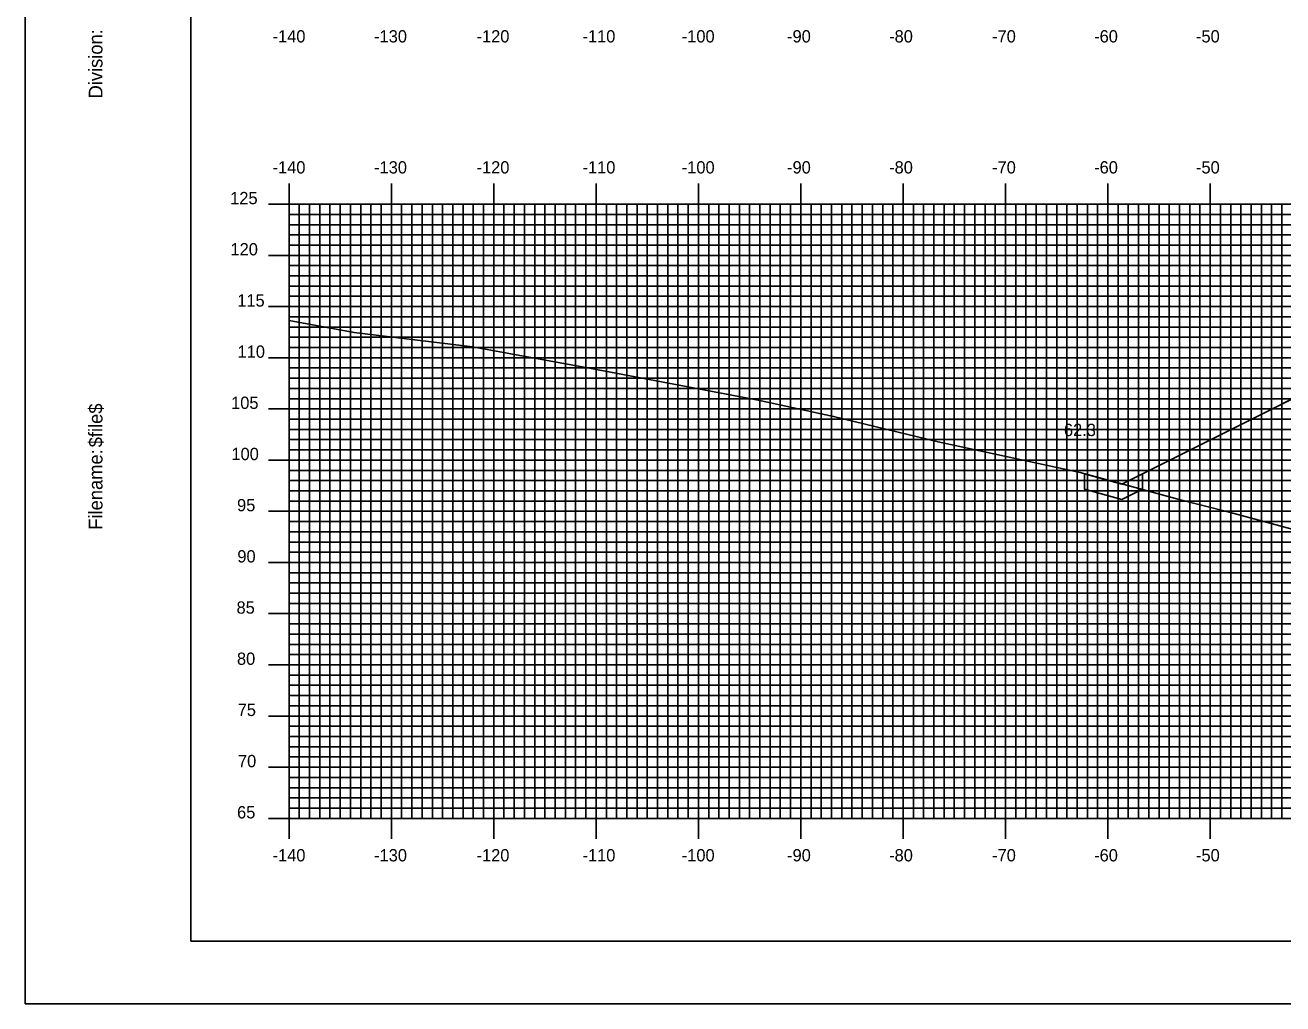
# Model space of a CAD drawing. Extents: x 858291 to 858634, y 364765 to 364985.
# Drawn here: x 858290.5 to 858413.4, y 364765.2 to 364860.8 of the extents above; entities that cross this region are included whole.
import ezdxf

# ---------------------------------------------------------------- set-up
doc = ezdxf.new("R2010")
doc.units = 0
for name, color, linetype in [('BORDER', 7, 'Continuous'), ('D_Roadway_Centerline', 7, 'Continuous'), ('D_Roadway_FinishedGrade', 7, 'Continuous'), ('D_Roadway_SlopeLines', 7, 'Continuous'), ('D_Text_Standard', 7, 'Continuous'), ('H_V ANNOTATION', 7, 'Continuous'), ('MAJOR', 7, 'Continuous'), ('MINOR', 7, 'Continuous'), ('PLOT BOUNDARY', 7, 'Continuous'), ('S_Roadway_Centerline', 7, 'Continuous')]:
    doc.layers.add(name, color=color, linetype=linetype)

msp = doc.modelspace()

# ---------------------------------------------------------------- linework, layer by layer
at = {"layer": 'BORDER'}
msp.add_lwpolyline([(858306.73, 364771.3), (858626.73, 364771.3), (858626.73, 364981.3), (858306.73, 364981.3)], close=True, dxfattribs=at)
at = {"layer": 'D_Roadway_Centerline'}
msp.add_lwpolyline([(858397.71, 364815.96), (858429.13, 364831.67), (858434.33, 364834.28), (858437.33, 364834.34), (858442.33, 364834.44), (858456.33, 364833.6), (858464.33, 364833.12), (858467.33, 364832.94), (858473.02, 364830.1), (858546.52, 364793.34)], dxfattribs=at)
at = {"layer": 'D_Roadway_FinishedGrade'}
for points in [[(858399.71, 364816.96), (858399.71, 364815.46), (858397.71, 364814.46), (858394.05, 364815.46), (858394.05, 364816.96), (858397.71, 364815.96)], [(858394.05, 364816.96), (858394.05, 364815.46), (858397.71, 364814.46), (858399.71, 364815.46), (858399.71, 364816.96), (858397.71, 364815.96)]]:
    msp.add_lwpolyline(points, close=True, dxfattribs=at)
at = {"layer": 'D_Roadway_SlopeLines'}
msp.add_lwpolyline([(858434.33, 364834.28), (858397.71, 364815.96)], dxfattribs=at)
at = {"layer": 'MAJOR'}
for p, q in [((858316.33, 364845.31), (858316.33, 364843.3)), ((858326.33, 364845.31), (858326.33, 364843.3)), ((858336.33, 364845.31), (858336.33, 364843.3)), ((858346.33, 364845.31), (858346.33, 364843.3)), ((858356.33, 364845.31), (858356.33, 364843.3)), ((858366.33, 364845.31), (858366.33, 364843.3)), ((858376.33, 364845.31), (858376.33, 364843.3)), ((858386.33, 364845.31), (858386.33, 364843.3)), ((858396.33, 364845.31), (858396.33, 364843.3)), ((858406.33, 364845.31), (858406.33, 364843.3)), ((858314.33, 364843.3), (858316.33, 364843.3)), ((858316.33, 364843.3), (858596.33, 364843.3)), ((858316.33, 364783.3), (858316.33, 364843.3)), ((858316.33, 364783.3), (858316.33, 364843.3)), ((858316.33, 364843.3), (858596.33, 364843.3)), ((858326.33, 364783.3), (858326.33, 364843.3)), ((858336.33, 364783.3), (858336.33, 364843.3)), ((858346.33, 364783.3), (858346.33, 364843.3)), ((858356.33, 364783.3), (858356.33, 364843.3)), ((858366.33, 364783.3), (858366.33, 364843.3)), ((858376.33, 364783.3), (858376.33, 364843.3)), ((858386.33, 364783.3), (858386.33, 364843.3)), ((858396.33, 364783.3), (858396.33, 364843.3)), ((858406.33, 364783.3), (858406.33, 364843.3)), ((858314.33, 364838.3), (858316.33, 364838.3)), ((858316.33, 364838.3), (858596.33, 364838.3)), ((858314.33, 364833.3), (858316.33, 364833.3)), ((858316.33, 364833.3), (858596.33, 364833.3)), ((858314.33, 364828.3), (858316.33, 364828.3)), ((858316.33, 364828.3), (858596.33, 364828.3)), ((858314.33, 364823.3), (858316.33, 364823.3)), ((858316.33, 364823.3), (858596.33, 364823.3)), ((858314.33, 364818.3), (858316.33, 364818.3)), ((858316.33, 364818.3), (858596.33, 364818.3)), ((858314.33, 364813.3), (858316.33, 364813.3)), ((858316.33, 364813.3), (858596.33, 364813.3)), ((858314.33, 364808.3), (858316.33, 364808.3)), ((858316.33, 364808.3), (858596.33, 364808.3)), ((858314.33, 364803.3), (858316.33, 364803.3)), ((858316.33, 364803.3), (858596.33, 364803.3)), ((858314.33, 364798.3), (858316.33, 364798.3)), ((858316.33, 364798.3), (858596.33, 364798.3)), ((858314.33, 364793.3), (858316.33, 364793.3)), ((858316.33, 364793.3), (858596.33, 364793.3)), ((858314.33, 364788.3), (858316.33, 364788.3)), ((858316.33, 364788.3), (858596.33, 364788.3)), ((858314.33, 364783.3), (858316.33, 364783.3)), ((858316.33, 364783.3), (858596.33, 364783.3)), ((858316.33, 364783.3), (858596.33, 364783.3)), ((858316.33, 364781.3), (858316.33, 364783.3)), ((858326.33, 364781.3), (858326.33, 364783.3)), ((858336.33, 364781.3), (858336.33, 364783.3)), ((858346.33, 364781.3), (858346.33, 364783.3)), ((858356.33, 364781.3), (858356.33, 364783.3)), ((858366.33, 364781.3), (858366.33, 364783.3)), ((858376.33, 364781.3), (858376.33, 364783.3)), ((858386.33, 364781.3), (858386.33, 364783.3)), ((858396.33, 364781.3), (858396.33, 364783.3)), ((858406.33, 364781.3), (858406.33, 364783.3))]:
    msp.add_line(p, q, dxfattribs=at)
at = {"layer": 'MINOR'}
for p, q in [((858316.33, 364842.3), (858596.33, 364842.3)), ((858316.33, 364842.3), (858318.34, 364842.3)), ((858317.33, 364783.3), (858317.33, 364843.3)), ((858318.33, 364783.3), (858318.33, 364843.3)), ((858319.33, 364783.3), (858319.33, 364843.3)), ((858320.33, 364783.3), (858320.33, 364843.3)), ((858321.33, 364783.3), (858321.33, 364843.3)), ((858322.33, 364783.3), (858322.33, 364843.3)), ((858323.33, 364783.3), (858323.33, 364843.3)), ((858324.33, 364783.3), (858324.33, 364843.3)), ((858325.33, 364783.3), (858325.33, 364843.3)), ((858327.33, 364783.3), (858327.33, 364843.3)), ((858328.33, 364783.3), (858328.33, 364843.3)), ((858329.33, 364783.3), (858329.33, 364843.3)), ((858330.33, 364783.3), (858330.33, 364843.3)), ((858331.33, 364783.3), (858331.33, 364843.3)), ((858332.33, 364783.3), (858332.33, 364843.3)), ((858333.33, 364783.3), (858333.33, 364843.3)), ((858334.33, 364783.3), (858334.33, 364843.3)), ((858335.33, 364783.3), (858335.33, 364843.3)), ((858337.33, 364783.3), (858337.33, 364843.3)), ((858338.33, 364783.3), (858338.33, 364843.3)), ((858339.33, 364783.3), (858339.33, 364843.3)), ((858340.33, 364783.3), (858340.33, 364843.3)), ((858341.33, 364783.3), (858341.33, 364843.3)), ((858342.33, 364783.3), (858342.33, 364843.3)), ((858343.33, 364783.3), (858343.33, 364843.3)), ((858344.33, 364783.3), (858344.33, 364843.3)), ((858345.33, 364783.3), (858345.33, 364843.3)), ((858347.33, 364783.3), (858347.33, 364843.3)), ((858348.33, 364783.3), (858348.33, 364843.3)), ((858349.33, 364783.3), (858349.33, 364843.3)), ((858350.33, 364783.3), (858350.33, 364843.3)), ((858351.33, 364783.3), (858351.33, 364843.3)), ((858352.33, 364783.3), (858352.33, 364843.3)), ((858353.33, 364783.3), (858353.33, 364843.3)), ((858354.33, 364783.3), (858354.33, 364843.3)), ((858355.33, 364783.3), (858355.33, 364843.3)), ((858357.33, 364783.3), (858357.33, 364843.3)), ((858358.33, 364783.3), (858358.33, 364843.3)), ((858359.33, 364783.3), (858359.33, 364843.3)), ((858360.33, 364783.3), (858360.33, 364843.3)), ((858361.33, 364783.3), (858361.33, 364843.3)), ((858362.33, 364783.3), (858362.33, 364843.3)), ((858363.33, 364783.3), (858363.33, 364843.3)), ((858364.33, 364783.3), (858364.33, 364843.3)), ((858365.33, 364783.3), (858365.33, 364843.3)), ((858367.33, 364783.3), (858367.33, 364843.3)), ((858368.33, 364783.3), (858368.33, 364843.3)), ((858369.33, 364783.3), (858369.33, 364843.3)), ((858370.33, 364783.3), (858370.33, 364843.3)), ((858371.33, 364783.3), (858371.33, 364843.3)), ((858372.33, 364783.3), (858372.33, 364843.3)), ((858373.33, 364783.3), (858373.33, 364843.3)), ((858374.33, 364783.3), (858374.33, 364843.3)), ((858375.33, 364783.3), (858375.33, 364843.3)), ((858377.33, 364783.3), (858377.33, 364843.3)), ((858378.33, 364783.3), (858378.33, 364843.3)), ((858379.33, 364783.3), (858379.33, 364843.3)), ((858380.33, 364783.3), (858380.33, 364843.3)), ((858381.33, 364783.3), (858381.33, 364843.3)), ((858382.33, 364783.3), (858382.33, 364843.3)), ((858383.33, 364783.3), (858383.33, 364843.3)), ((858384.33, 364783.3), (858384.33, 364843.3)), ((858385.33, 364783.3), (858385.33, 364843.3)), ((858387.33, 364783.3), (858387.33, 364843.3)), ((858388.33, 364783.3), (858388.33, 364843.3)), ((858389.33, 364783.3), (858389.33, 364843.3)), ((858390.33, 364783.3), (858390.33, 364843.3)), ((858391.33, 364783.3), (858391.33, 364843.3)), ((858392.33, 364783.3), (858392.33, 364843.3)), ((858393.33, 364783.3), (858393.33, 364843.3)), ((858394.33, 364783.3), (858394.33, 364843.3)), ((858395.33, 364783.3), (858395.33, 364843.3)), ((858397.33, 364783.3), (858397.33, 364843.3)), ((858398.33, 364783.3), (858398.33, 364843.3)), ((858399.33, 364783.3), (858399.33, 364843.3)), ((858400.33, 364783.3), (858400.33, 364843.3)), ((858401.33, 364783.3), (858401.33, 364843.3)), ((858402.33, 364783.3), (858402.33, 364843.3)), ((858403.33, 364783.3), (858403.33, 364843.3)), ((858404.33, 364783.3), (858404.33, 364843.3)), ((858405.33, 364783.3), (858405.33, 364843.3)), ((858407.33, 364783.3), (858407.33, 364843.3)), ((858408.33, 364783.3), (858408.33, 364843.3)), ((858409.33, 364783.3), (858409.33, 364843.3)), ((858410.33, 364783.3), (858410.33, 364843.3)), ((858411.33, 364783.3), (858411.33, 364843.3)), ((858412.33, 364783.3), (858412.33, 364843.3)), ((858413.33, 364783.3), (858413.33, 364843.3)), ((858316.33, 364841.3), (858596.33, 364841.3)), ((858316.33, 364841.3), (858318.34, 364841.3)), ((858316.33, 364840.3), (858596.33, 364840.3)), ((858316.33, 364840.3), (858318.34, 364840.3)), ((858316.33, 364839.3), (858596.33, 364839.3)), ((858316.33, 364839.3), (858318.34, 364839.3)), ((858316.33, 364837.3), (858596.33, 364837.3)), ((858316.33, 364837.3), (858318.34, 364837.3)), ((858316.33, 364836.3), (858596.33, 364836.3)), ((858316.33, 364836.3), (858318.34, 364836.3)), ((858316.33, 364835.3), (858596.33, 364835.3)), ((858316.33, 364835.3), (858318.34, 364835.3)), ((858316.33, 364834.3), (858596.33, 364834.3)), ((858316.33, 364834.3), (858318.34, 364834.3)), ((858316.33, 364832.3), (858596.33, 364832.3)), ((858316.33, 364832.3), (858318.34, 364832.3)), ((858316.33, 364831.3), (858596.33, 364831.3)), ((858316.33, 364831.3), (858318.34, 364831.3)), ((858316.33, 364830.3), (858596.33, 364830.3)), ((858316.33, 364830.3), (858318.34, 364830.3)), ((858316.33, 364829.3), (858596.33, 364829.3)), ((858316.33, 364829.3), (858318.34, 364829.3)), ((858316.33, 364827.3), (858596.33, 364827.3)), ((858316.33, 364827.3), (858318.34, 364827.3)), ((858316.33, 364826.3), (858596.33, 364826.3)), ((858316.33, 364826.3), (858318.34, 364826.3)), ((858316.33, 364825.3), (858596.33, 364825.3)), ((858316.33, 364825.3), (858318.34, 364825.3)), ((858316.33, 364824.3), (858596.33, 364824.3)), ((858316.33, 364824.3), (858318.34, 364824.3)), ((858316.33, 364822.3), (858596.33, 364822.3)), ((858316.33, 364822.3), (858318.34, 364822.3)), ((858316.33, 364821.3), (858596.33, 364821.3)), ((858316.33, 364821.3), (858318.34, 364821.3)), ((858316.33, 364820.3), (858596.33, 364820.3)), ((858316.33, 364820.3), (858318.34, 364820.3)), ((858316.33, 364819.3), (858596.33, 364819.3)), ((858316.33, 364819.3), (858318.34, 364819.3)), ((858316.33, 364817.3), (858596.33, 364817.3)), ((858316.33, 364817.3), (858318.34, 364817.3)), ((858316.33, 364816.3), (858596.33, 364816.3)), ((858316.33, 364816.3), (858318.34, 364816.3)), ((858316.33, 364815.3), (858596.33, 364815.3)), ((858316.33, 364815.3), (858318.34, 364815.3)), ((858316.33, 364814.3), (858596.33, 364814.3)), ((858316.33, 364814.3), (858318.34, 364814.3)), ((858316.33, 364812.3), (858596.33, 364812.3)), ((858316.33, 364812.3), (858318.34, 364812.3)), ((858316.33, 364811.3), (858596.33, 364811.3)), ((858316.33, 364811.3), (858318.34, 364811.3)), ((858316.33, 364810.3), (858596.33, 364810.3)), ((858316.33, 364810.3), (858318.34, 364810.3)), ((858316.33, 364809.3), (858596.33, 364809.3)), ((858316.33, 364809.3), (858318.34, 364809.3)), ((858316.33, 364807.3), (858596.33, 364807.3)), ((858316.33, 364807.3), (858318.34, 364807.3)), ((858316.33, 364806.3), (858596.33, 364806.3)), ((858316.33, 364806.3), (858318.34, 364806.3)), ((858316.33, 364805.3), (858596.33, 364805.3)), ((858316.33, 364805.3), (858318.34, 364805.3)), ((858316.33, 364804.3), (858596.33, 364804.3)), ((858316.33, 364804.3), (858318.34, 364804.3)), ((858316.33, 364802.3), (858596.33, 364802.3)), ((858316.33, 364802.3), (858318.34, 364802.3)), ((858316.33, 364801.3), (858596.33, 364801.3)), ((858316.33, 364801.3), (858318.34, 364801.3)), ((858316.33, 364800.3), (858596.33, 364800.3)), ((858316.33, 364800.3), (858318.34, 364800.3)), ((858316.33, 364799.3), (858596.33, 364799.3)), ((858316.33, 364799.3), (858318.34, 364799.3)), ((858316.33, 364797.3), (858596.33, 364797.3)), ((858316.33, 364797.3), (858318.34, 364797.3)), ((858316.33, 364796.3), (858596.33, 364796.3)), ((858316.33, 364796.3), (858318.34, 364796.3)), ((858316.33, 364795.3), (858596.33, 364795.3)), ((858316.33, 364795.3), (858318.34, 364795.3)), ((858316.33, 364794.3), (858596.33, 364794.3)), ((858316.33, 364794.3), (858318.34, 364794.3)), ((858316.33, 364792.3), (858596.33, 364792.3)), ((858316.33, 364792.3), (858318.34, 364792.3)), ((858316.33, 364791.3), (858596.33, 364791.3)), ((858316.33, 364791.3), (858318.34, 364791.3)), ((858316.33, 364790.3), (858596.33, 364790.3)), ((858316.33, 364790.3), (858318.34, 364790.3)), ((858316.33, 364789.3), (858596.33, 364789.3)), ((858316.33, 364789.3), (858318.34, 364789.3)), ((858316.33, 364787.3), (858596.33, 364787.3)), ((858316.33, 364787.3), (858318.34, 364787.3)), ((858316.33, 364786.3), (858596.33, 364786.3)), ((858316.33, 364786.3), (858318.34, 364786.3)), ((858316.33, 364785.3), (858596.33, 364785.3)), ((858316.33, 364785.3), (858318.34, 364785.3)), ((858316.33, 364784.3), (858596.33, 364784.3)), ((858316.33, 364784.3), (858318.34, 364784.3))]:
    msp.add_line(p, q, dxfattribs=at)
at = {"layer": 'PLOT BOUNDARY'}
msp.add_lwpolyline([(858290.55, 364765.18), (858630.55, 364765.18), (858630.55, 364985.18), (858290.55, 364985.18)], close=True, dxfattribs=at)
at = {"layer": 'S_Roadway_Centerline'}
msp.add_lwpolyline([(858316.33, 364831.94), (858322.68, 364830.77), (858334.25, 364829.38), (858341.37, 364828.07), (858345.86, 364827.25), (858362.16, 364824.16), (858369.53, 364822.57), (858379.74, 364820.08), (858393.63, 364817.08), (858403.29, 364814.44), (858408.18, 364813.22), (858422.53, 364809.35)], dxfattribs=at)

# ---------------------------------------------------------------- texts
at = {"layer": 'BORDER'}
for s, p in [('Division:', (858298.1, 364853.63)), ('$file$', (858298.1, 364819.55)), ('Filename:', (858298.1, 364811.5))]:
    msp.add_text(s, height=1.339, rotation=90, dxfattribs=at).set_placement(p)
at = {"layer": 'D_Text_Standard'}
msp.add_text("62.3'", height=1.2, dxfattribs=at).set_placement((858392.04, 364820.65))
at = {"layer": 'H_V ANNOTATION'}
for s, p in [('-140', (858314.72, 364859.1)), ('-130', (858324.64, 364859.1)), ('-120', (858334.65, 364859.1)), ('-110', (858345, 364859.1)), ('-100', (858354.7, 364859.1)), ('-90', (858364.99, 364859.1)), ('-80', (858374.96, 364859.1)), ('-70', (858385.02, 364859.1)), ('-60', (858394.99, 364859.1)), ('-50', (858404.94, 364859.1)), ('-140', (858314.72, 364846.3)), ('-130', (858324.64, 364846.3)), ('-120', (858334.65, 364846.3)), ('-110', (858345, 364846.3)), ('-100', (858354.7, 364846.3)), ('-90', (858364.99, 364846.3)), ('-80', (858374.96, 364846.3)), ('-70', (858385.02, 364846.3)), ('-60', (858394.99, 364846.3)), ('-50', (858404.94, 364846.3)), ('125', (858310.58, 364843.3)), ('120', (858310.61, 364838.3)), ('115', (858311.27, 364833.3)), ('110', (858311.3, 364828.3)), ('105', (858310.67, 364823.3)), ('100', (858310.7, 364818.3)), ('95', (858311.25, 364813.3)), ('90', (858311.28, 364808.3)), ('85', (858311.2, 364803.3)), ('80', (858311.24, 364798.3)), ('75', (858311.31, 364793.3)), ('70', (858311.34, 364788.3)), ('65', (858311.25, 364783.3)), ('-140', (858314.72, 364779.1)), ('-130', (858324.64, 364779.1)), ('-120', (858334.65, 364779.1)), ('-110', (858345, 364779.1)), ('-100', (858354.7, 364779.1)), ('-90', (858364.99, 364779.1)), ('-80', (858374.96, 364779.1)), ('-70', (858385.02, 364779.1)), ('-60', (858394.99, 364779.1)), ('-50', (858404.94, 364779.1))]:
    msp.add_text(s, height=1.2, dxfattribs=at).set_placement(p)
at = {"layer": 'MAJOR'}
msp.add_text('-', height=0.012, dxfattribs=at).set_placement((858316.32, 364783.3))

doc.saveas('drawing.dxf')
